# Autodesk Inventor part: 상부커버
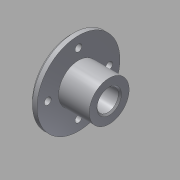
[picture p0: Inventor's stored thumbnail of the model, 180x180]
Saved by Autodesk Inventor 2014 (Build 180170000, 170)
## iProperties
Created: 2015-09
Part Number: 상부커버
Material: 알루미늄 6061
Document SubType Name: Modeling
Designer: mduedu
Density: 1 g/cm^3
Appearance: 알루미늄 - 평지
Author: mduedu
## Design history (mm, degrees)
sketch "스케치1"
  geometry: L1 (-12.5, 0)-(12.5, 0); L2 (-12.5, 0)-(-12.5, 27); L3 (-12.5, 27)-(-7.5, 27); L4 (-7.5, 27)-(-7.5, 13); L5 (-7.5, 13)-(12.5, 13); L6 (12.5, 13)-(12.5, 0); 2 further points
  constraints: 12 end point, 2 parallel, 2 perpendicular, 1 coincident, 1 horizontal, 1 midpoint, 1 vertical
  dimensions: "d0" = 25 distance of L1.start L1.end; "d2" = 5 distance of L2.end L3.end; "d3" = 26 diameter of L5 L1; "d4" = 54 diameter of L3 L1
revolve "회전1" sketch "스케치1" stored, may be unused: angle "d5" = 90 deg
hole "구멍1" diameter "d8" = 14; stored, may be unused: countersink angle "d12" = 90 deg, drill point angle "d14" = 118 deg; dims "d6" = 10, "d7" = 10, "d9" = 6, "d10" = 4, "d11" = 2, "d13" = 8
chamfer "모따기1" distance "d15" = 1; stored, may be unused: second distance "d16" = 2, angle "d17" = 45 deg
chamfer "모따기2" distance "d18" = 2; stored, may be unused: second distance "d19" = 2, angle "d20" = 45 deg
sketch "스케치2" dims "d21" = 40
  geometry: 6 further points
  constraints: 2 vertical alignment, 1 coincident, 7 other
  dimensions: "d25" = 360 deg dimension on point (0, 0) point (0, 20) (derived)
sketch "스케치3"
  geometry: 4 further points
hole "구멍2" sketch "스케치3" at (0, 20), (-20, 0), (20, 0), (0, -20) diameter "d27" = 4.5; stored, may be unused: countersink angle "d31" = 90 deg, drill point angle "d33" = 0 deg; dims "d28" = 6, "d29" = 4, "d30" = 2, "d32" = 8
node "솔리드1"
